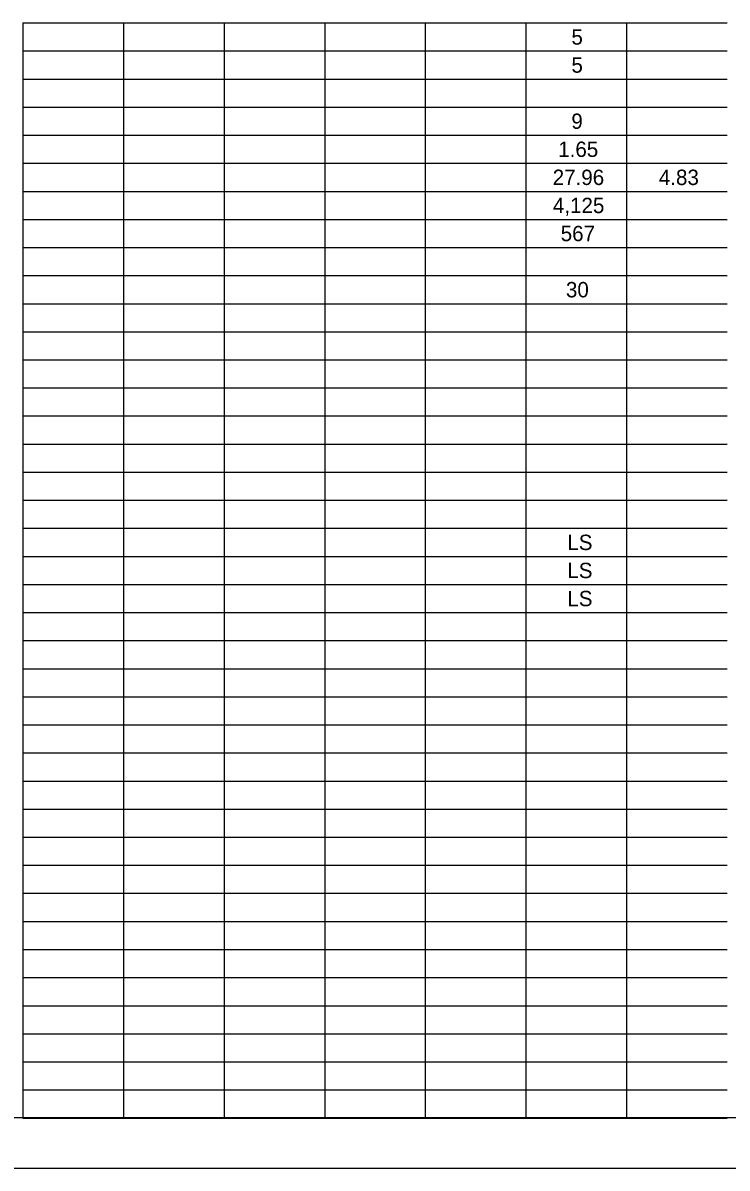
# Model space of a CAD drawing. Extents: x 0 to 34, y 0 to 22.
# Drawn here: x 8.52 to 15.54, y 0 to 11.42 of the extents above; entities that cross this region are included whole.
import ezdxf

# ---------------------------------------------------------------- set-up
doc = ezdxf.new("R2010")
doc.units = 0
for name, color, linetype in [('SH_Border', 7, 'Continuous'), ('SH_Cut_Line', 7, 'Continuous'), ('SH_Text', 7, 'Continuous')]:
    doc.layers.add(name, color=color, linetype=linetype)

msp = doc.modelspace()

# ---------------------------------------------------------------- linework, layer by layer
at = {"layer": 'SH_Border'}
msp.add_lwpolyline([(1.5, 21.5), (33.5, 21.5), (33.5, 0.5), (1.5, 0.5)], close=True, dxfattribs=at)
at = {"layer": 'SH_Cut_Line'}
msp.add_lwpolyline([(0, 0), (34, 0), (34, 22), (0, 22)], close=True, dxfattribs=at)
at = {"layer": 'SH_Text'}
for p, q in [((8.519, 11.42), (9.521, 11.42)), ((8.519, 11.42), (8.519, 10.3)), ((9.521, 11.42), (11.527, 11.42)), ((9.521, 11.42), (9.521, 10.3)), ((10.524, 11.42), (10.524, 10.3)), ((11.527, 11.42), (12.529, 11.42)), ((11.527, 11.42), (11.527, 10.3)), ((12.529, 11.42), (13.532, 11.42)), ((12.529, 11.42), (12.529, 10.3)), ((13.532, 11.42), (14.535, 11.42)), ((13.532, 11.42), (13.532, 10.3)), ((14.535, 11.42), (15.537, 11.42)), ((14.535, 11.42), (14.535, 10.3)), ((8.519, 11.14), (9.521, 11.14)), ((9.521, 11.14), (11.527, 11.14)), ((11.527, 11.14), (12.529, 11.14)), ((12.529, 11.14), (13.532, 11.14)), ((13.532, 11.14), (14.535, 11.14)), ((14.535, 11.14), (15.537, 11.14)), ((8.519, 10.86), (9.521, 10.86)), ((9.521, 10.86), (11.527, 10.86)), ((11.527, 10.86), (12.529, 10.86)), ((12.529, 10.86), (13.532, 10.86)), ((13.532, 10.86), (14.535, 10.86)), ((14.535, 10.86), (15.537, 10.86)), ((8.519, 10.58), (9.521, 10.58)), ((9.521, 10.58), (11.527, 10.58)), ((11.527, 10.58), (12.529, 10.58)), ((12.529, 10.58), (13.532, 10.58)), ((13.532, 10.58), (14.535, 10.58)), ((14.535, 10.58), (15.537, 10.58)), ((8.519, 10.3), (9.521, 10.3)), ((8.519, 10.3), (8.519, 10.02)), ((9.521, 10.3), (11.527, 10.3)), ((9.521, 10.3), (9.521, 10.02)), ((10.524, 10.3), (10.524, 10.02)), ((11.527, 10.3), (12.529, 10.3)), ((11.527, 10.3), (11.527, 10.02)), ((12.529, 10.3), (13.532, 10.3)), ((12.529, 10.3), (12.529, 10.02)), ((13.532, 10.3), (14.535, 10.3)), ((13.532, 10.3), (13.532, 10.02)), ((14.535, 10.3), (15.537, 10.3)), ((14.535, 10.3), (14.535, 10.02)), ((8.519, 10.02), (9.521, 10.02)), ((8.519, 10.02), (8.519, 9.74)), ((9.521, 10.02), (11.527, 10.02)), ((9.521, 10.02), (9.521, 9.74)), ((10.524, 10.02), (10.524, 9.74)), ((11.527, 10.02), (12.529, 10.02)), ((11.527, 10.02), (11.527, 9.74)), ((12.529, 10.02), (13.532, 10.02)), ((12.529, 10.02), (12.529, 9.74)), ((13.532, 10.02), (14.535, 10.02)), ((13.532, 10.02), (13.532, 9.74)), ((14.535, 10.02), (15.537, 10.02)), ((14.535, 10.02), (14.535, 9.74)), ((8.519, 9.74), (9.521, 9.74)), ((8.519, 9.74), (8.519, 8.9)), ((9.521, 9.74), (11.527, 9.74)), ((9.521, 9.74), (9.521, 8.9)), ((10.524, 9.74), (10.524, 8.9)), ((11.527, 9.74), (12.529, 9.74)), ((11.527, 9.74), (11.527, 8.9)), ((12.529, 9.74), (13.532, 9.74)), ((12.529, 9.74), (12.529, 8.9)), ((13.532, 9.74), (14.535, 9.74)), ((13.532, 9.74), (13.532, 8.9)), ((14.535, 9.74), (15.537, 9.74)), ((14.535, 9.74), (14.535, 8.9)), ((8.519, 9.46), (9.521, 9.46)), ((9.521, 9.46), (11.527, 9.46)), ((11.527, 9.46), (12.529, 9.46)), ((12.529, 9.46), (13.532, 9.46)), ((13.532, 9.46), (14.535, 9.46)), ((14.535, 9.46), (15.537, 9.46)), ((8.519, 9.18), (9.521, 9.18)), ((9.521, 9.18), (11.527, 9.18)), ((11.527, 9.18), (12.529, 9.18)), ((12.529, 9.18), (13.532, 9.18)), ((13.532, 9.18), (14.535, 9.18)), ((14.535, 9.18), (15.537, 9.18)), ((8.519, 8.9), (9.521, 8.9)), ((8.519, 8.9), (8.519, 8.34)), ((9.521, 8.9), (11.527, 8.9)), ((9.521, 8.9), (9.521, 8.34)), ((10.524, 8.9), (10.524, 8.34)), ((11.527, 8.9), (12.529, 8.9)), ((11.527, 8.9), (11.527, 8.34)), ((12.529, 8.9), (13.532, 8.9)), ((12.529, 8.9), (12.529, 8.34)), ((13.532, 8.9), (14.535, 8.9)), ((13.532, 8.9), (13.532, 8.34)), ((14.535, 8.9), (15.537, 8.9)), ((14.535, 8.9), (14.535, 8.34)), ((8.519, 8.62), (9.521, 8.62)), ((9.521, 8.62), (11.527, 8.62)), ((11.527, 8.62), (12.529, 8.62)), ((12.529, 8.62), (13.532, 8.62)), ((13.532, 8.62), (14.535, 8.62)), ((14.535, 8.62), (15.537, 8.62)), ((8.519, 8.34), (9.521, 8.34)), ((8.519, 8.34), (8.519, 7.5)), ((9.521, 8.34), (11.527, 8.34)), ((9.521, 8.34), (9.521, 7.5)), ((10.524, 8.34), (10.524, 7.5)), ((11.527, 8.34), (12.529, 8.34)), ((11.527, 8.34), (11.527, 7.5)), ((12.529, 8.34), (13.532, 8.34)), ((12.529, 8.34), (12.529, 7.5)), ((13.532, 8.34), (14.535, 8.34)), ((13.532, 8.34), (13.532, 7.5)), ((14.535, 8.34), (15.537, 8.34)), ((14.535, 8.34), (14.535, 7.5)), ((8.519, 8.06), (9.521, 8.06)), ((9.521, 8.06), (11.527, 8.06)), ((11.527, 8.06), (12.529, 8.06)), ((12.529, 8.06), (13.532, 8.06)), ((13.532, 8.06), (14.535, 8.06)), ((14.535, 8.06), (15.537, 8.06)), ((8.519, 7.78), (9.521, 7.78)), ((9.521, 7.78), (11.527, 7.78)), ((11.527, 7.78), (12.529, 7.78)), ((12.529, 7.78), (13.532, 7.78)), ((13.532, 7.78), (14.535, 7.78)), ((14.535, 7.78), (15.537, 7.78)), ((8.519, 7.5), (9.521, 7.5)), ((8.519, 7.5), (8.519, 6.94)), ((9.521, 7.5), (11.527, 7.5)), ((9.521, 7.5), (9.521, 6.94)), ((10.524, 7.5), (10.524, 6.94)), ((11.527, 7.5), (12.529, 7.5)), ((11.527, 7.5), (11.527, 6.94)), ((12.529, 7.5), (13.532, 7.5)), ((12.529, 7.5), (12.529, 6.94)), ((13.532, 7.5), (14.535, 7.5)), ((13.532, 7.5), (13.532, 6.94)), ((14.535, 7.5), (15.537, 7.5)), ((14.535, 7.5), (14.535, 6.94)), ((8.519, 7.22), (9.521, 7.22)), ((9.521, 7.22), (11.527, 7.22)), ((11.527, 7.22), (12.529, 7.22)), ((12.529, 7.22), (13.532, 7.22)), ((13.532, 7.22), (14.535, 7.22)), ((14.535, 7.22), (15.537, 7.22)), ((8.519, 6.94), (9.521, 6.94)), ((8.519, 6.94), (8.519, 6.1)), ((9.521, 6.94), (11.527, 6.94)), ((9.521, 6.94), (9.521, 6.1)), ((10.524, 6.94), (10.524, 6.1)), ((11.527, 6.94), (12.529, 6.94)), ((11.527, 6.94), (11.527, 6.1)), ((12.529, 6.94), (13.532, 6.94)), ((12.529, 6.94), (12.529, 6.1)), ((13.532, 6.94), (14.535, 6.94)), ((13.532, 6.94), (13.532, 6.1)), ((14.535, 6.94), (15.537, 6.94)), ((14.535, 6.94), (14.535, 6.1)), ((8.519, 6.66), (9.521, 6.66)), ((9.521, 6.66), (11.527, 6.66)), ((11.527, 6.66), (12.529, 6.66)), ((12.529, 6.66), (13.532, 6.66)), ((13.532, 6.66), (14.535, 6.66)), ((14.535, 6.66), (15.537, 6.66)), ((8.519, 6.38), (9.521, 6.38)), ((9.521, 6.38), (11.527, 6.38)), ((11.527, 6.38), (12.529, 6.38)), ((12.529, 6.38), (13.532, 6.38)), ((13.532, 6.38), (14.535, 6.38)), ((14.535, 6.38), (15.537, 6.38)), ((8.519, 6.1), (9.521, 6.1)), ((8.519, 6.1), (8.519, 4.98)), ((9.521, 6.1), (11.527, 6.1)), ((9.521, 6.1), (9.521, 4.98)), ((10.524, 6.1), (10.524, 4.98)), ((11.527, 6.1), (12.529, 6.1)), ((11.527, 6.1), (11.527, 4.98)), ((12.529, 6.1), (13.532, 6.1)), ((12.529, 6.1), (12.529, 4.98)), ((13.532, 6.1), (14.535, 6.1)), ((13.532, 6.1), (13.532, 4.98)), ((14.535, 6.1), (15.537, 6.1)), ((14.535, 6.1), (14.535, 4.98)), ((8.519, 5.82), (9.521, 5.82)), ((9.521, 5.82), (11.527, 5.82)), ((11.527, 5.82), (12.529, 5.82)), ((12.529, 5.82), (13.532, 5.82)), ((13.532, 5.82), (14.535, 5.82)), ((14.535, 5.82), (15.537, 5.82)), ((8.519, 5.54), (9.521, 5.54)), ((9.521, 5.54), (11.527, 5.54)), ((11.527, 5.54), (12.529, 5.54)), ((12.529, 5.54), (13.532, 5.54)), ((13.532, 5.54), (14.535, 5.54)), ((14.535, 5.54), (15.537, 5.54)), ((8.519, 5.26), (9.521, 5.26)), ((9.521, 5.26), (11.527, 5.26)), ((11.527, 5.26), (12.529, 5.26)), ((12.529, 5.26), (13.532, 5.26)), ((13.532, 5.26), (14.535, 5.26)), ((14.535, 5.26), (15.537, 5.26)), ((8.519, 4.98), (9.521, 4.98)), ((8.519, 4.98), (8.519, 4.7)), ((9.521, 4.98), (11.527, 4.98)), ((9.521, 4.98), (9.521, 4.7)), ((10.524, 4.98), (10.524, 4.7)), ((11.527, 4.98), (12.529, 4.98)), ((11.527, 4.98), (11.527, 4.7)), ((12.529, 4.98), (13.532, 4.98)), ((12.529, 4.98), (12.529, 4.7)), ((13.532, 4.98), (14.535, 4.98)), ((13.532, 4.98), (13.532, 4.7)), ((14.535, 4.98), (15.537, 4.98)), ((14.535, 4.98), (14.535, 4.7)), ((8.519, 4.7), (9.521, 4.7)), ((8.519, 4.7), (8.519, 3.58)), ((9.521, 4.7), (11.527, 4.7)), ((9.521, 4.7), (9.521, 3.58)), ((10.524, 4.7), (10.524, 3.58)), ((11.527, 4.7), (12.529, 4.7)), ((11.527, 4.7), (11.527, 3.58)), ((12.529, 4.7), (13.532, 4.7)), ((12.529, 4.7), (12.529, 3.58)), ((13.532, 4.7), (14.535, 4.7)), ((13.532, 4.7), (13.532, 3.58)), ((14.535, 4.7), (15.537, 4.7)), ((14.535, 4.7), (14.535, 3.58)), ((8.519, 4.42), (9.521, 4.42)), ((9.521, 4.42), (11.527, 4.42)), ((11.527, 4.42), (12.529, 4.42)), ((12.529, 4.42), (13.532, 4.42)), ((13.532, 4.42), (14.535, 4.42)), ((14.535, 4.42), (15.537, 4.42)), ((8.519, 4.14), (9.521, 4.14)), ((9.521, 4.14), (11.527, 4.14)), ((11.527, 4.14), (12.529, 4.14)), ((12.529, 4.14), (13.532, 4.14)), ((13.532, 4.14), (14.535, 4.14)), ((14.535, 4.14), (15.537, 4.14)), ((8.519, 3.86), (9.521, 3.86)), ((9.521, 3.86), (11.527, 3.86)), ((11.527, 3.86), (12.529, 3.86)), ((12.529, 3.86), (13.532, 3.86)), ((13.532, 3.86), (14.535, 3.86)), ((14.535, 3.86), (15.537, 3.86)), ((8.519, 3.58), (9.521, 3.58)), ((8.519, 3.58), (8.519, 3.3)), ((9.521, 3.58), (11.527, 3.58)), ((9.521, 3.58), (9.521, 3.3)), ((10.524, 3.58), (10.524, 3.3)), ((11.527, 3.58), (12.529, 3.58)), ((11.527, 3.58), (11.527, 3.3)), ((12.529, 3.58), (13.532, 3.58)), ((12.529, 3.58), (12.529, 3.3)), ((13.532, 3.58), (14.535, 3.58)), ((13.532, 3.58), (13.532, 3.3)), ((14.535, 3.58), (15.537, 3.58)), ((14.535, 3.58), (14.535, 3.3)), ((8.519, 3.3), (9.521, 3.3)), ((8.519, 3.3), (8.519, 2.179)), ((9.521, 3.3), (11.527, 3.3)), ((9.521, 3.3), (9.521, 2.179)), ((10.524, 3.3), (10.524, 2.179)), ((11.527, 3.3), (12.529, 3.3)), ((11.527, 3.3), (11.527, 2.179)), ((12.529, 3.3), (13.532, 3.3)), ((12.529, 3.3), (12.529, 2.179)), ((13.532, 3.3), (14.535, 3.3)), ((13.532, 3.3), (13.532, 2.179)), ((14.535, 3.3), (15.537, 3.3)), ((14.535, 3.3), (14.535, 2.179)), ((8.519, 3.02), (9.521, 3.02)), ((9.521, 3.02), (11.527, 3.02)), ((11.527, 3.02), (12.529, 3.02)), ((12.529, 3.02), (13.532, 3.02)), ((13.532, 3.02), (14.535, 3.02)), ((14.535, 3.02), (15.537, 3.02)), ((8.519, 2.74), (9.521, 2.74)), ((9.521, 2.74), (11.527, 2.74)), ((11.527, 2.74), (12.529, 2.74)), ((12.529, 2.74), (13.532, 2.74)), ((13.532, 2.74), (14.535, 2.74)), ((14.535, 2.74), (15.537, 2.74)), ((8.519, 2.46), (9.521, 2.46)), ((9.521, 2.46), (11.527, 2.46)), ((11.527, 2.46), (12.529, 2.46)), ((12.529, 2.46), (13.532, 2.46)), ((13.532, 2.46), (14.535, 2.46)), ((14.535, 2.46), (15.537, 2.46)), ((8.519, 2.179), (9.521, 2.179)), ((8.519, 2.179), (8.519, 1.899)), ((9.521, 2.179), (11.527, 2.179)), ((9.521, 2.179), (9.521, 1.899)), ((10.524, 2.179), (10.524, 1.899)), ((11.527, 2.179), (12.529, 2.179)), ((11.527, 2.179), (11.527, 1.899)), ((12.529, 2.179), (13.532, 2.179)), ((12.529, 2.179), (12.529, 1.899)), ((13.532, 2.179), (14.535, 2.179)), ((13.532, 2.179), (13.532, 1.899)), ((14.535, 2.179), (15.537, 2.179)), ((14.535, 2.179), (14.535, 1.899)), ((8.519, 1.899), (9.521, 1.899)), ((8.519, 1.899), (8.519, 0.779)), ((9.521, 1.899), (11.527, 1.899)), ((9.521, 1.899), (9.521, 0.779)), ((10.524, 1.899), (10.524, 0.779)), ((11.527, 1.899), (12.529, 1.899)), ((11.527, 1.899), (11.527, 0.779)), ((12.529, 1.899), (13.532, 1.899)), ((12.529, 1.899), (12.529, 0.779)), ((13.532, 1.899), (14.535, 1.899)), ((13.532, 1.899), (13.532, 0.779)), ((14.535, 1.899), (15.537, 1.899)), ((14.535, 1.899), (14.535, 0.779)), ((8.519, 1.619), (9.521, 1.619)), ((9.521, 1.619), (11.527, 1.619)), ((11.527, 1.619), (12.529, 1.619)), ((12.529, 1.619), (13.532, 1.619)), ((13.532, 1.619), (14.535, 1.619)), ((14.535, 1.619), (15.537, 1.619)), ((8.519, 1.339), (9.521, 1.339)), ((9.521, 1.339), (11.527, 1.339)), ((11.527, 1.339), (12.529, 1.339)), ((12.529, 1.339), (13.532, 1.339)), ((13.532, 1.339), (14.535, 1.339)), ((14.535, 1.339), (15.537, 1.339)), ((8.519, 1.059), (9.521, 1.059)), ((9.521, 1.059), (11.527, 1.059)), ((11.527, 1.059), (12.529, 1.059)), ((12.529, 1.059), (13.532, 1.059)), ((13.532, 1.059), (14.535, 1.059)), ((14.535, 1.059), (15.537, 1.059)), ((8.519, 0.779), (9.521, 0.779)), ((8.519, 0.779), (8.519, 0.499)), ((9.521, 0.779), (11.527, 0.779)), ((9.521, 0.779), (9.521, 0.499)), ((10.524, 0.779), (10.524, 0.499)), ((11.527, 0.779), (12.529, 0.779)), ((11.527, 0.779), (11.527, 0.499)), ((12.529, 0.779), (13.532, 0.779)), ((12.529, 0.779), (12.529, 0.499)), ((13.532, 0.779), (14.535, 0.779)), ((13.532, 0.779), (13.532, 0.499)), ((14.535, 0.779), (15.537, 0.779)), ((14.535, 0.779), (14.535, 0.499)), ((8.519, 0.499), (9.521, 0.499)), ((9.521, 0.499), (11.527, 0.499)), ((11.527, 0.499), (12.529, 0.499)), ((12.529, 0.499), (13.532, 0.499)), ((13.532, 0.499), (14.535, 0.499)), ((14.535, 0.499), (15.537, 0.499))]:
    msp.add_line(p, q, dxfattribs=at)

# ---------------------------------------------------------------- texts
for s, height, p in [('5', 0.153, (13.986, 11.203)), ('5', 0.153, (13.986, 10.923)), ('9', 0.153, (13.985, 10.363)), ('1.65', 0.1533, (13.854, 10.083)), ('27.96', 0.1533, (13.799, 9.803)), ('4.83', 0.1533, (14.857, 9.803)), ('4,125', 0.1533, (13.801, 9.523)), ('567', 0.1533, (13.879, 9.243)), ('30', 0.1533, (13.931, 8.683)), ('LS', 0.1533, (13.945, 6.163)), ('LS', 0.1533, (13.945, 5.883)), ('LS', 0.1533, (13.945, 5.603))]:
    msp.add_text(s, height=height, dxfattribs=at).set_placement(p)

doc.saveas('drawing.dxf')
